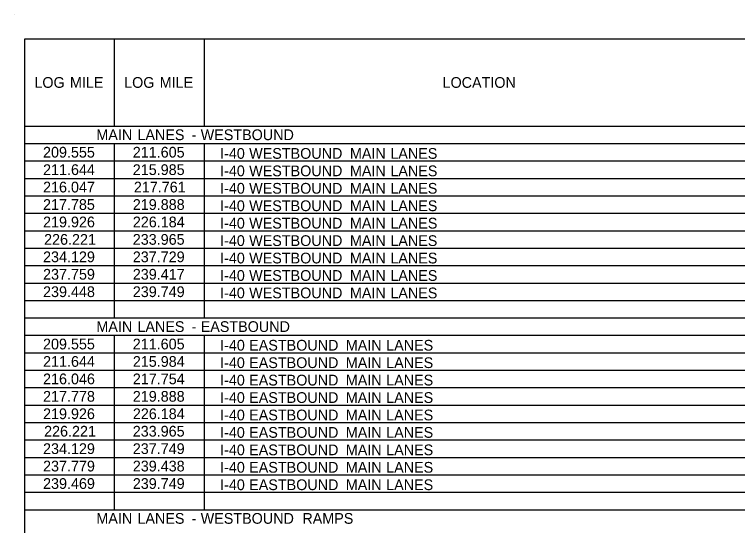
# Model space of a CAD drawing. Extents: x 2261867 to 2275370, y -3124789 to -3122260.
# Drawn here: x 2269374.6 to 2269779.2, y -3122546 to -3122260.2 of the extents above; entities that cross this region are included whole.
import ezdxf

# ---------------------------------------------------------------- set-up
doc = ezdxf.new("R2010")
doc.units = 0
doc.layers.add('Default', color=7, linetype='Continuous')

msp = doc.modelspace()

# ---------------------------------------------------------------- linework, layer by layer
at = {"layer": 'Default'}
for p, q in [((2269374.62, -3122260.2), (2269374.62, -3122260.2)), ((2269380.47, -3122273.85), (2270507.08, -3122273.85)), ((2269380.47, -3123434.1), (2269380.47, -3122273.85)), ((2269380.47, -3123434.1), (2269380.47, -3122273.85)), ((2269430.68, -3122322.6), (2269430.68, -3122273.85)), ((2269480.89, -3122322.6), (2269480.89, -3122273.85)), ((2269380.47, -3122322.6), (2270507.08, -3122322.6)), ((2269380.47, -3122332.35), (2270507.08, -3122332.35)), ((2269430.68, -3122429.85), (2269430.68, -3122332.35)), ((2269430.68, -3122429.85), (2269430.68, -3122332.35)), ((2269480.89, -3122429.85), (2269480.89, -3122332.35)), ((2269480.89, -3122429.85), (2269480.89, -3122332.35)), ((2269380.47, -3122342.1), (2270507.08, -3122342.1)), ((2269380.47, -3122351.85), (2270507.08, -3122351.85)), ((2269380.47, -3122361.6), (2270507.08, -3122361.6)), ((2269380.47, -3122371.35), (2270507.08, -3122371.35)), ((2269380.47, -3122381.1), (2270507.08, -3122381.1)), ((2269380.47, -3122390.85), (2270507.08, -3122390.85)), ((2269380.47, -3122400.6), (2270507.08, -3122400.6)), ((2269380.47, -3122410.35), (2270507.08, -3122410.35)), ((2269380.47, -3122420.1), (2270507.08, -3122420.1)), ((2269380.47, -3122429.85), (2270507.08, -3122429.85)), ((2269380.47, -3122429.85), (2270507.08, -3122429.85)), ((2269380.47, -3122439.6), (2270507.08, -3122439.6)), ((2269430.68, -3122537.1), (2269430.68, -3122439.6)), ((2269430.68, -3122537.1), (2269430.68, -3122439.6)), ((2269480.89, -3122537.1), (2269480.89, -3122439.6)), ((2269480.89, -3122537.1), (2269480.89, -3122439.6)), ((2269380.47, -3122449.35), (2270507.08, -3122449.35)), ((2269380.47, -3122459.1), (2270507.08, -3122459.1)), ((2269380.47, -3122468.85), (2270507.08, -3122468.85)), ((2269380.47, -3122478.6), (2270507.08, -3122478.6)), ((2269380.47, -3122488.35), (2270507.08, -3122488.35)), ((2269380.47, -3122498.1), (2270507.08, -3122498.1)), ((2269380.47, -3122507.85), (2270507.08, -3122507.85)), ((2269380.47, -3122517.6), (2270507.08, -3122517.6)), ((2269380.47, -3122527.35), (2270507.08, -3122527.35)), ((2269380.47, -3122537.1), (2270507.08, -3122537.1)), ((2269380.47, -3122537.1), (2270507.08, -3122537.1))]:
    msp.add_line(p, q, dxfattribs=at)

# ---------------------------------------------------------------- texts
for s, p in [('LOG', (2269385.78, -3122301.22)), (' MILE', (2269403.44, -3122301.22)), ('LOG', (2269435.99, -3122301.22)), (' MILE', (2269453.65, -3122301.22)), ('LOCATION', (2269614.12, -3122301.22)), ('MAIN', (2269420.44, -3122330.47)), (' LANES', (2269441.19, -3122330.47)), (' WESTBOUND', (2269476.58, -3122330.47)), (' -', (2269471.53, -3122330.47)), ('209.555', (2269390.6, -3122340.22)), ('211.605', (2269440.81, -3122340.22)), ('I-40', (2269489.67, -3122340.9)), (' WESTBOUND', (2269503.7, -3122340.9)), (' MAIN', (2269560.08, -3122340.9)), (' LANES', (2269582.68, -3122340.9)), ('211.644', (2269390.63, -3122349.97)), ('215.985', (2269440.81, -3122349.97)), ('I-40', (2269489.67, -3122350.65)), (' WESTBOUND', (2269503.7, -3122350.65)), (' MAIN', (2269560.08, -3122350.65)), (' LANES', (2269582.68, -3122350.65)), ('216.047', (2269390.62, -3122359.72)), ('217.761', (2269441.41, -3122359.72)), ('I-40', (2269489.67, -3122360.4)), (' WESTBOUND', (2269503.7, -3122360.4)), (' MAIN', (2269560.08, -3122360.4)), (' LANES', (2269582.68, -3122360.4)), ('217.785', (2269390.6, -3122369.47)), ('219.888', (2269440.83, -3122369.47)), ('I-40', (2269489.67, -3122370.15)), (' WESTBOUND', (2269503.7, -3122370.15)), (' MAIN', (2269560.08, -3122370.15)), (' LANES', (2269582.68, -3122370.15)), ('219.926', (2269390.62, -3122379.22)), ('226.184', (2269440.85, -3122379.22)), ('I-40', (2269489.67, -3122379.9)), (' WESTBOUND', (2269503.7, -3122379.9)), (' MAIN', (2269560.08, -3122379.9)), (' LANES', (2269582.68, -3122379.9)), ('226.221', (2269391.2, -3122388.97)), ('233.965', (2269440.81, -3122388.97)), ('I-40', (2269489.67, -3122389.65)), (' WESTBOUND', (2269503.7, -3122389.65)), (' MAIN', (2269560.08, -3122389.65)), (' LANES', (2269582.68, -3122389.65)), ('234.129', (2269390.62, -3122398.72)), ('237.729', (2269440.83, -3122398.72)), ('I-40', (2269489.67, -3122399.4)), (' WESTBOUND', (2269503.7, -3122399.4)), (' MAIN', (2269560.08, -3122399.4)), (' LANES', (2269582.68, -3122399.4)), ('237.759', (2269390.62, -3122408.47)), ('239.417', (2269440.83, -3122408.47)), ('I-40', (2269489.67, -3122409.15)), (' WESTBOUND', (2269503.7, -3122409.15)), (' MAIN', (2269560.08, -3122409.15)), (' LANES', (2269582.68, -3122409.15)), ('239.448', (2269390.62, -3122418.22)), ('239.749', (2269440.83, -3122418.22)), ('I-40', (2269489.67, -3122418.9)), (' WESTBOUND', (2269503.7, -3122418.9)), (' MAIN', (2269560.08, -3122418.9)), (' LANES', (2269582.68, -3122418.9)), ('MAIN', (2269420.44, -3122437.72)), (' LANES', (2269441.19, -3122437.72)), (' EASTBOUND', (2269476.58, -3122437.72)), (' -', (2269471.53, -3122437.72)), ('209.555', (2269390.6, -3122447.47)), ('211.605', (2269440.81, -3122447.47)), ('I-40', (2269489.67, -3122448.15)), (' EASTBOUND', (2269503.7, -3122448.15)), (' MAIN', (2269557.76, -3122448.15)), (' LANES', (2269580.36, -3122448.15)), ('211.644', (2269390.63, -3122457.22)), ('215.984', (2269440.85, -3122457.22)), ('I-40', (2269489.67, -3122457.9)), (' EASTBOUND', (2269503.7, -3122457.9)), (' MAIN', (2269557.76, -3122457.9)), (' LANES', (2269580.36, -3122457.9)), ('216.046', (2269390.62, -3122466.97)), ('217.754', (2269440.85, -3122466.97)), ('I-40', (2269489.67, -3122467.65)), (' EASTBOUND', (2269503.7, -3122467.65)), (' MAIN', (2269557.76, -3122467.65)), (' LANES', (2269580.36, -3122467.65)), ('217.778', (2269390.62, -3122476.72)), ('219.888', (2269440.83, -3122476.72)), ('I-40', (2269489.67, -3122477.4)), (' EASTBOUND', (2269503.7, -3122477.4)), (' MAIN', (2269557.76, -3122477.4)), (' LANES', (2269580.36, -3122477.4)), ('219.926', (2269390.62, -3122486.47)), ('226.184', (2269440.85, -3122486.47)), ('I-40', (2269489.67, -3122487.15)), (' EASTBOUND', (2269503.7, -3122487.15)), (' MAIN', (2269557.76, -3122487.15)), (' LANES', (2269580.36, -3122487.15)), ('226.221', (2269391.2, -3122496.22)), ('233.965', (2269440.81, -3122496.22)), ('I-40', (2269489.67, -3122496.9)), (' EASTBOUND', (2269503.7, -3122496.9)), (' MAIN', (2269557.76, -3122496.9)), (' LANES', (2269580.36, -3122496.9)), ('234.129', (2269390.62, -3122505.97)), ('237.749', (2269440.83, -3122505.97)), ('I-40', (2269489.67, -3122506.65)), (' EASTBOUND', (2269503.7, -3122506.65)), (' MAIN', (2269557.76, -3122506.65)), (' LANES', (2269580.36, -3122506.65)), ('237.779', (2269390.62, -3122515.72)), ('239.438', (2269440.83, -3122515.72)), ('I-40', (2269489.67, -3122516.4)), (' EASTBOUND', (2269503.7, -3122516.4)), (' MAIN', (2269557.76, -3122516.4)), (' LANES', (2269580.36, -3122516.4)), ('239.469', (2269390.62, -3122525.47)), ('239.749', (2269440.83, -3122525.47)), ('I-40', (2269489.67, -3122526.15)), (' EASTBOUND', (2269503.7, -3122526.15)), (' MAIN', (2269557.76, -3122526.15)), (' LANES', (2269580.36, -3122526.15)), ('MAIN', (2269420.44, -3122544.97)), (' LANES', (2269441.19, -3122544.97)), (' WESTBOUND', (2269476.58, -3122544.97)), (' RAMPS', (2269533.46, -3122544.97)), (' -', (2269471.53, -3122544.97))]:
    msp.add_text(s, height=6, dxfattribs=at).set_placement(p)

doc.saveas('drawing.dxf')
